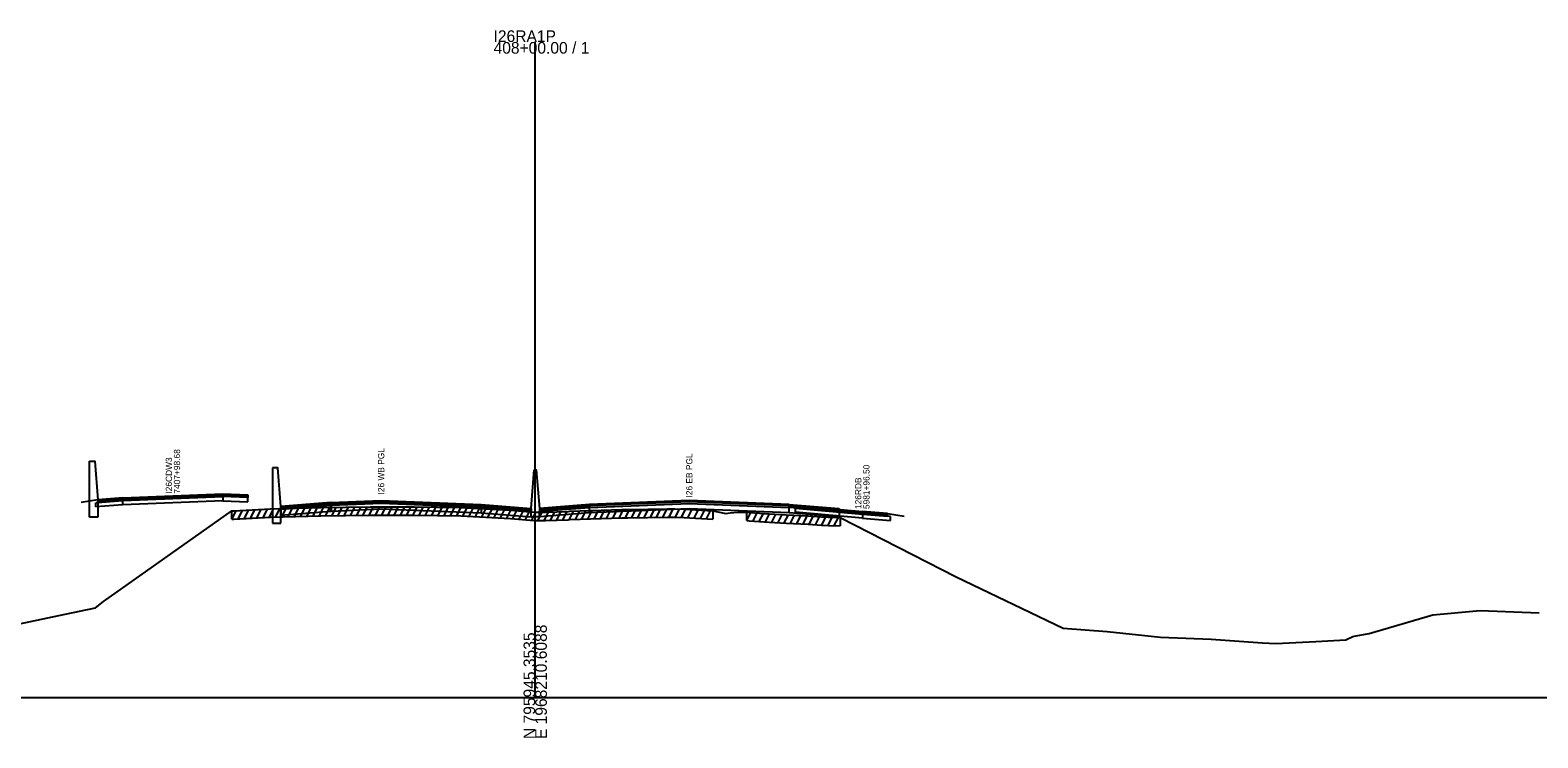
# Model space of a CAD drawing. Extents: x 1017 to 19997, y -1947 to 50737.
# Drawn here: x 16478.7 to 16840.8, y 7990.3 to 8160.2 of the extents above; entities that cross this region are included whole.
import ezdxf

# ---------------------------------------------------------------- set-up
doc = ezdxf.new("R2010")
doc.units = 0
for name, color, linetype in [('RD_GPK_XS_Cell', 7, 'Continuous'), ('RD_XS_Base', 7, 'Continuous'), ('RD_XS_ExGround', 7, 'Continuous'), ('RD_XS_ExPaveRet', 7, 'Continuous'), ('RD_XS_Greenside', 7, 'Continuous'), ('RD_XS_MedBWall', 7, 'Continuous'), ('RD_XS_Pave', 7, 'Continuous'), ('RD_XS_PaveOvlay', 7, 'Continuous'), ('RD_XS_TX_Notes', 7, 'Continuous')]:
    doc.layers.add(name, color=color, linetype=linetype)

msp = doc.modelspace()

# ---------------------------------------------------------------- linework, layer by layer
at = {"layer": 'RD_GPK_XS_Cell'}
for p, q in [((16600, 8000), (16600, 8157.32)), ((16000, 8000), (16600, 8000)), ((16600, 8000), (17200, 8000))]:
    msp.add_line(p, q, dxfattribs=at)
at = {"layer": 'RD_XS_Base'}
for points in [[(16494.5, 8046.74), (16495, 8046.78), (16501, 8047.26)], [(16494.5, 8045.74), (16494.5, 8046.74)], [(16501, 8046.26), (16494.5, 8045.74)], [(16501, 8046.26), (16501, 8047.26)], [(16525, 8047.22), (16513, 8046.74), (16501, 8046.26)], [(16525, 8048.22), (16525, 8047.22)], [(16525, 8047.22), (16531, 8046.96)], [(16531, 8046.96), (16531, 8047.96)], [(16550.95, 8046.09), (16538.95, 8045.13)], [(16538.95, 8045.13), (16538.95, 8043.79)], [(16550.95, 8044.75), (16550.95, 8046.09)], [(16551, 8046.09), (16551, 8044.75)], [(16551, 8044.75), (16563, 8045.24), (16587, 8044.28)], [(16599, 8044.68), (16587, 8045.62)], [(16587, 8045.62), (16587, 8044.28)], [(16613, 8044.28), (16613, 8045.62)], [(16660.95, 8044.28), (16637, 8045.24), (16613, 8044.28)], [(16660.95, 8044.28), (16660.95, 8045.62)], [(16661, 8044.28), (16661, 8045.62)], [(16662.52, 8044.47), (16662.52, 8045.47)], [(16538.95, 8043.79), (16550.95, 8044.75)], [(16551, 8044.75), (16550.95, 8044.75)], [(16587, 8044.28), (16599, 8043.34)], [(16599, 8043.34), (16599, 8044.68)], [(16601, 8043.34), (16601, 8044.68)], [(16613, 8044.28), (16601, 8043.34)], [(16661, 8044.28), (16660.95, 8044.28)], [(16673, 8043.32), (16661, 8044.28)], [(16678.58, 8043.02), (16662.52, 8044.47)], [(16673, 8044.66), (16673, 8043.32)], [(16678.58, 8044.02), (16678.58, 8043.02)], [(16685.3, 8043.46), (16684.6, 8043.52), (16678.58, 8044.02)], [(16678.58, 8043.02), (16685.3, 8042.46)], [(16685.3, 8042.46), (16685.3, 8043.46)]]:
    msp.add_lwpolyline(points, dxfattribs=at)
at = {"layer": 'RD_XS_ExGround'}
msp.add_lwpolyline([(16474.65, 8017.34), (16487.14, 8019.98), (16494.38, 8021.48), (16496.32, 8023.03), (16527.16, 8044.76), (16527.63, 8044.79), (16536.47, 8045.25), (16548.53, 8045.56), (16560.44, 8045.79), (16570.97, 8045.77), (16576.53, 8045.68), (16582.15, 8045.59), (16594.06, 8044.98), (16599.79, 8044.51), (16602.44, 8044.48), (16607.91, 8044.66), (16608.35, 8044.68), (16620.8, 8045.09), (16622.21, 8045.12), (16631.78, 8045.29), (16632.21, 8045.29), (16633.5, 8045.3), (16635.74, 8045.18), (16642.68, 8044.76), (16644.64, 8044.39), (16645.73, 8044.19), (16646.78, 8044.28), (16648.63, 8044.51), (16649.51, 8044.47), (16650.82, 8044.46), (16651.42, 8044.43), (16652.69, 8044.33), (16656.18, 8044.1), (16660.27, 8043.85), (16665.56, 8043.56), (16668.76, 8043.36), (16670.43, 8043.31), (16673.26, 8043.17), (16701.12, 8028.95), (16726.76, 8016.64), (16737.34, 8015.8), (16750.13, 8014.43), (16762.31, 8014), (16774.66, 8013.07), (16777.89, 8012.92), (16787.46, 8013.42), (16794.64, 8013.82), (16796.32, 8014.59), (16796.67, 8014.71), (16800.29, 8015.35), (16815.6, 8019.86), (16826.96, 8020.83), (16841.12, 8020.34)], dxfattribs=at)
at = {"layer": 'RD_XS_ExPaveRet'}
for p, q in [((16531.66, 8043), (16532.69, 8045.05)), ((16533.16, 8043.08), (16534.19, 8045.13)), ((16534.66, 8043.16), (16535.69, 8045.21)), ((16536.16, 8043.24), (16537.18, 8045.27)), ((16537.66, 8043.28), (16538.67, 8045.31)), ((16539.16, 8043.32), (16540.17, 8045.35)), ((16540.66, 8043.36), (16541.67, 8045.39)), ((16542.16, 8043.4), (16543.17, 8045.43)), ((16543.66, 8043.44), (16544.67, 8045.46)), ((16545.16, 8043.48), (16546.17, 8045.5)), ((16546.66, 8043.52), (16547.67, 8045.54)), ((16548.16, 8043.55), (16549.17, 8045.58)), ((16549.66, 8043.58), (16550.67, 8045.6)), ((16551.16, 8043.61), (16552.17, 8045.63)), ((16552.66, 8043.64), (16553.67, 8045.66)), ((16554.16, 8043.67), (16555.17, 8045.69)), ((16555.66, 8043.7), (16556.67, 8045.72)), ((16557.16, 8043.73), (16558.17, 8045.75)), ((16558.66, 8043.75), (16559.67, 8045.77)), ((16560.16, 8043.78), (16561.16, 8045.79)), ((16561.66, 8043.79), (16562.66, 8045.79)), ((16563.16, 8043.78), (16564.16, 8045.78)), ((16564.66, 8043.78), (16565.66, 8045.78)), ((16566.16, 8043.78), (16567.16, 8045.78)), ((16567.66, 8043.78), (16568.66, 8045.78)), ((16569.16, 8043.77), (16570.16, 8045.77)), ((16570.66, 8043.77), (16571.65, 8045.76)), ((16572.16, 8043.75), (16573.15, 8045.74)), ((16573.66, 8043.73), (16574.65, 8045.71)), ((16575.16, 8043.7), (16576.15, 8045.69)), ((16576.66, 8043.68), (16577.65, 8045.66)), ((16578.16, 8043.66), (16579.15, 8045.64)), ((16579.66, 8043.63), (16580.65, 8045.62)), ((16581.16, 8043.61), (16582.15, 8045.59)), ((16582.66, 8043.57), (16583.63, 8045.52)), ((16584.16, 8043.49), (16585.13, 8045.44)), ((16585.66, 8043.41), (16586.63, 8045.36)), ((16587.16, 8043.33), (16588.13, 8045.28)), ((16588.66, 8043.26), (16589.63, 8045.2)), ((16590.16, 8043.18), (16591.13, 8045.13)), ((16591.66, 8043.1), (16592.63, 8045.05)), ((16618.66, 8043.02), (16619.68, 8045.05)), ((16620.16, 8043.07), (16621.17, 8045.1)), ((16621.66, 8043.11), (16622.67, 8045.12)), ((16623.16, 8043.13), (16624.17, 8045.15)), ((16624.66, 8043.16), (16625.67, 8045.18)), ((16626.16, 8043.19), (16627.17, 8045.21)), ((16627.66, 8043.21), (16628.67, 8045.23)), ((16629.16, 8043.24), (16630.17, 8045.26)), ((16630.66, 8043.27), (16631.67, 8045.29)), ((16632.16, 8043.29), (16633.16, 8045.29)), ((16633.66, 8043.29), (16634.63, 8045.24)), ((16635.16, 8043.21), (16636.13, 8045.16)), ((16636.66, 8043.12), (16637.63, 8045.06)), ((16527.16, 8042.76), (16528.19, 8044.82)), ((16527.16, 8042.76), (16527.16, 8044.76)), ((16527.16, 8042.76), (16527.63, 8042.79)), ((16527.63, 8042.79), (16536.47, 8043.25)), ((16528.66, 8042.84), (16529.69, 8044.89)), ((16530.16, 8042.92), (16531.19, 8044.97)), ((16536.47, 8043.25), (16548.53, 8043.56)), ((16548.53, 8043.56), (16560.44, 8043.79)), ((16560.44, 8043.79), (16570.97, 8043.77)), ((16570.97, 8043.77), (16576.53, 8043.68)), ((16576.53, 8043.68), (16582.15, 8043.59)), ((16582.15, 8043.59), (16594.06, 8042.98)), ((16593.16, 8043.02), (16594.13, 8044.97)), ((16594.06, 8042.98), (16599.79, 8042.51)), ((16594.66, 8042.93), (16595.62, 8044.85)), ((16596.16, 8042.81), (16597.12, 8044.73)), ((16597.66, 8042.68), (16598.62, 8044.61)), ((16599.16, 8042.56), (16600.13, 8044.51)), ((16599.79, 8042.51), (16602.44, 8042.48)), ((16600.66, 8042.5), (16601.65, 8044.49)), ((16602.16, 8042.49), (16603.17, 8044.51)), ((16602.44, 8042.48), (16607.91, 8042.66)), ((16603.66, 8042.52), (16604.68, 8044.56)), ((16605.16, 8042.57), (16606.18, 8044.61)), ((16606.66, 8042.62), (16607.68, 8044.66)), ((16607.91, 8042.66), (16608.35, 8042.68)), ((16608.16, 8042.67), (16609.18, 8044.71)), ((16608.35, 8042.68), (16620.8, 8043.09)), ((16609.66, 8042.72), (16610.68, 8044.76)), ((16611.16, 8042.77), (16612.18, 8044.8)), ((16612.66, 8042.82), (16613.68, 8044.85)), ((16614.16, 8042.87), (16615.18, 8044.9)), ((16615.66, 8042.92), (16616.68, 8044.95)), ((16617.16, 8042.97), (16618.18, 8045)), ((16620.8, 8043.09), (16622.21, 8043.12)), ((16622.21, 8043.12), (16631.78, 8043.29)), ((16631.78, 8043.29), (16632.21, 8043.29)), ((16632.21, 8043.29), (16633.5, 8043.3)), ((16633.5, 8043.3), (16635.74, 8043.18)), ((16635.74, 8043.18), (16642.68, 8042.76)), ((16638.16, 8043.03), (16639.13, 8044.97)), ((16639.66, 8042.94), (16640.63, 8044.88)), ((16641.16, 8042.85), (16642.13, 8044.79)), ((16642.68, 8044.76), (16642.68, 8042.76)), ((16650.82, 8042.46), (16650.82, 8044.46)), ((16650.82, 8042.46), (16651.79, 8044.4)), ((16650.82, 8042.46), (16651.42, 8042.43)), ((16651.42, 8042.43), (16652.69, 8042.33)), ((16652.32, 8042.36), (16653.29, 8044.29)), ((16652.69, 8042.33), (16656.18, 8042.1)), ((16653.82, 8042.26), (16654.79, 8044.19)), ((16655.32, 8042.16), (16656.29, 8044.09)), ((16656.18, 8042.1), (16660.27, 8041.85)), ((16656.82, 8042.06), (16657.79, 8044)), ((16658.32, 8041.97), (16659.29, 8043.91)), ((16659.82, 8041.88), (16660.79, 8043.83)), ((16660.27, 8041.85), (16665.56, 8041.56)), ((16661.32, 8041.8), (16662.3, 8043.74)), ((16662.82, 8041.71), (16663.8, 8043.66)), ((16664.32, 8041.63), (16665.3, 8043.58)), ((16665.56, 8041.56), (16668.76, 8041.36)), ((16665.82, 8041.55), (16666.79, 8043.48)), ((16667.32, 8041.45), (16668.29, 8043.39)), ((16668.82, 8041.36), (16669.81, 8043.33)), ((16670.32, 8041.31), (16671.3, 8043.27)), ((16671.82, 8041.24), (16672.8, 8043.19)), ((16673.26, 8043.17), (16673.26, 8041.17)), ((16668.76, 8041.36), (16670.43, 8041.31)), ((16670.43, 8041.31), (16673.26, 8041.17))]:
    msp.add_line(p, q, dxfattribs=at)
at = {"layer": 'RD_XS_Greenside'}
for points in [[(16495, 8047.41), (16491, 8046.77)], [(16684.6, 8044.15), (16688.61, 8043.5)]]:
    msp.add_lwpolyline(points, dxfattribs=at)
at = {"layer": 'RD_XS_MedBWall'}
for points in [[(16493, 8043.27), (16493, 8056.75)], [(16493, 8056.75), (16494.25, 8056.75), (16495, 8047.41)], [(16538.95, 8045.81), (16538.2, 8055.15), (16536.95, 8055.15)], [(16536.95, 8055.15), (16536.95, 8041.81)], [(16599, 8045.33), (16599.75, 8054.67)], [(16599.75, 8054.67), (16600.25, 8054.67), (16601, 8045.33)], [(16495, 8047.41), (16495, 8043.27)], [(16538.95, 8041.81), (16538.95, 8045.81)], [(16599, 8043.33), (16599, 8044.68), (16599, 8045.33)], [(16601, 8045.33), (16601, 8044.68), (16601, 8043.33)], [(16495, 8043.27), (16493, 8043.27)], [(16536.95, 8041.81), (16538.95, 8041.81)], [(16601, 8043.33), (16599, 8043.33)]]:
    msp.add_lwpolyline(points, dxfattribs=at)
at = {"layer": 'RD_XS_Pave'}
for points in [[(16495, 8047.1), (16501, 8047.58)], [(16501, 8047.26), (16495, 8046.78)], [(16495, 8046.78), (16495, 8047.1)], [(16525, 8048.54), (16513, 8048.06), (16501, 8047.58)], [(16501, 8047.26), (16513, 8047.74), (16525, 8048.22)], [(16501, 8047.58), (16501, 8047.26)], [(16525, 8048.22), (16525, 8048.54)], [(16525, 8048.54), (16531, 8048.29)], [(16531, 8047.96), (16525, 8048.22)], [(16531, 8048.29), (16531, 8047.96)], [(16550.95, 8046.43), (16538.95, 8045.47)], [(16538.95, 8045.47), (16538.95, 8045.13)], [(16550.95, 8046.43), (16551, 8046.43)], [(16550.95, 8046.09), (16550.95, 8046.43)], [(16551, 8046.09), (16550.95, 8046.09)], [(16587, 8045.62), (16563, 8046.58), (16551, 8046.09)], [(16551, 8046.43), (16551, 8046.09)], [(16587, 8045.96), (16587, 8045.62)], [(16587, 8045.96), (16599, 8045.02)], [(16599, 8045.02), (16599, 8044.68)], [(16601, 8044.68), (16613, 8045.62)], [(16601, 8045.02), (16601, 8044.68)], [(16660.95, 8045.96), (16637, 8046.92), (16613, 8045.96)], [(16613, 8045.62), (16637, 8046.58), (16660.95, 8045.62)], [(16613, 8045.96), (16613, 8045.62)], [(16660.95, 8045.96), (16661, 8045.96)], [(16660.95, 8045.62), (16660.95, 8045.96)], [(16661, 8045.62), (16660.95, 8045.62)], [(16661, 8045.96), (16661, 8045.62)], [(16673, 8044.66), (16661, 8045.62)], [(16678.58, 8044.34), (16662.52, 8045.78)], [(16662.52, 8045.78), (16662.52, 8045.47)], [(16662.52, 8045.47), (16678.58, 8044.02)], [(16673, 8045), (16673, 8044.66)], [(16678.58, 8044.02), (16678.58, 8044.34)], [(16684.6, 8043.84), (16678.58, 8044.34)], [(16678.58, 8044.02), (16684.6, 8043.52)], [(16684.6, 8043.52), (16684.6, 8043.84)]]:
    msp.add_lwpolyline(points, dxfattribs=at)
at = {"layer": 'RD_XS_PaveOvlay'}
for points in [[(16501, 8047.89), (16513, 8048.37), (16525, 8048.85)], [(16525, 8048.85), (16525, 8048.54)], [(16525, 8048.85), (16531, 8048.61)], [(16501, 8047.89), (16495, 8047.41)], [(16495, 8047.41), (16495, 8047.1)], [(16501, 8047.58), (16501, 8047.89)], [(16531, 8048.61), (16531, 8048.29)], [(16550.95, 8046.77), (16538.95, 8045.81)], [(16538.95, 8045.81), (16538.95, 8045.47)], [(16551, 8046.77), (16550.95, 8046.77)], [(16550.95, 8046.77), (16550.95, 8046.43)], [(16551, 8046.77), (16563, 8047.25), (16587, 8046.29)], [(16587, 8045.96), (16563, 8046.92), (16551, 8046.43)], [(16551, 8046.43), (16551, 8046.77)], [(16587, 8046.29), (16587, 8045.96)], [(16587, 8046.29), (16599, 8045.33)], [(16599, 8045.33), (16599, 8045.02)], [(16613, 8046.29), (16601, 8045.33)], [(16601, 8045.02), (16613, 8045.96)], [(16601, 8045.33), (16601, 8045.02)], [(16660.95, 8046.29), (16637, 8047.25), (16613, 8046.29)], [(16613, 8045.96), (16613, 8046.29)], [(16660.95, 8046.29), (16661, 8046.29)], [(16660.95, 8045.96), (16660.95, 8046.29)], [(16661, 8046.29), (16673, 8045.33)], [(16661, 8045.96), (16661, 8046.29)], [(16673, 8045), (16661, 8045.96)], [(16662.52, 8046.1), (16678.58, 8044.66)], [(16662.52, 8045.78), (16662.52, 8046.1)], [(16673, 8045.33), (16673, 8045)], [(16678.58, 8044.66), (16678.58, 8044.34)], [(16684.6, 8044.15), (16678.58, 8044.66)], [(16684.6, 8043.84), (16684.6, 8044.15)]]:
    msp.add_lwpolyline(points, dxfattribs=at)

# ---------------------------------------------------------------- texts
at = {"layer": 'RD_GPK_XS_Cell'}
for s, p in [('408+00.00 / 1', (16590, 8154.52)), ('I26RA1P', (16590, 8157.32))]:
    msp.add_text(s, height=2.8, dxfattribs=at).set_placement(p)
for s, p in [('E 1968210.6088', (16602.8, 7990)), ('N 795945.3535', (16600, 7990))]:
    msp.add_text(s, height=2.8, rotation=90, dxfattribs=at).set_placement(p)
at = {"layer": 'RD_XS_TX_Notes'}
for s, p in [('I26 WB PGL', (16563.75, 8048.72)), (' I26CDW3', (16512.78, 8048.37)), (' 7407+98.68', (16514.73, 8048.37)), ('I26 EB PGL', (16637.75, 8047.99)), (' 126RDB', (16678.32, 8044.66)), (' 5981+96.50', (16680.28, 8044.66))]:
    msp.add_text(s, height=1.5, rotation=90, dxfattribs=at).set_placement(p)

doc.saveas('drawing.dxf')
